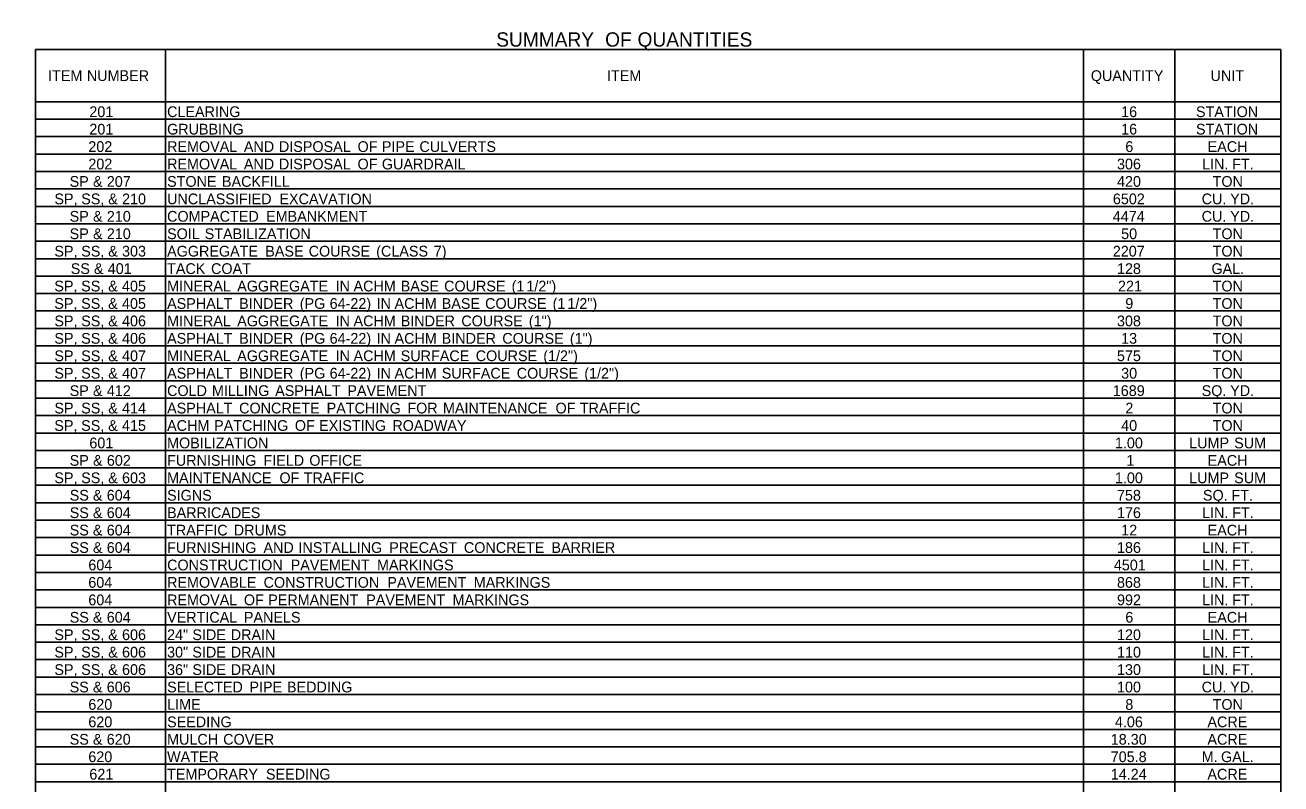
# Model space of a CAD drawing. Extents: x 1955554 to 1962042, y 565952 to 568347.
# Drawn here: x 1960905 to 1961607, y 566475 to 566899 of the extents above; entities that cross this region are included whole.
import ezdxf

# ---------------------------------------------------------------- set-up
doc = ezdxf.new("R2010")
doc.units = 0
doc.layers.add('Default', color=7, linetype='Continuous')

msp = doc.modelspace()

# ---------------------------------------------------------------- linework, layer by layer
at = {"layer": 'Default'}
for p, q in [((1960904.85, 566899.44), (1960904.85, 566899.44)), ((1960910.7, 566885.79), (1960983.24, 566885.79)), ((1960910.7, 566885.79), (1961606.85, 566885.79)), ((1960910.7, 566213.04), (1960910.7, 566885.79)), ((1960910.7, 566213.04), (1960910.7, 566885.79)), ((1960983.24, 566310.54), (1960983.24, 566885.79)), ((1961496.48, 566213.04), (1961496.48, 566885.79)), ((1961547.57, 566213.04), (1961547.57, 566885.79)), ((1961547.57, 566310.54), (1961547.57, 566885.79)), ((1961606.85, 566213.04), (1961606.85, 566885.79)), ((1960910.7, 566856.54), (1961606.85, 566856.54)), ((1960983.24, 566310.54), (1960983.24, 566856.54)), ((1961496.48, 566310.54), (1961496.48, 566856.54)), ((1960910.7, 566846.79), (1961606.85, 566846.79)), ((1960910.7, 566837.04), (1961606.85, 566837.04)), ((1960910.7, 566827.29), (1961606.85, 566827.29)), ((1960910.7, 566817.54), (1961606.85, 566817.54)), ((1960910.7, 566807.79), (1961606.85, 566807.79)), ((1960910.7, 566798.04), (1961606.85, 566798.04)), ((1960910.7, 566788.29), (1961606.85, 566788.29)), ((1960910.7, 566778.54), (1961606.85, 566778.54)), ((1960910.7, 566768.79), (1961606.85, 566768.79)), ((1960910.7, 566759.04), (1961606.85, 566759.04)), ((1960910.7, 566749.29), (1961606.85, 566749.29)), ((1960910.7, 566739.54), (1961606.85, 566739.54)), ((1960910.7, 566729.79), (1961606.85, 566729.79)), ((1960910.7, 566720.04), (1961606.85, 566720.04)), ((1960910.7, 566710.29), (1961606.85, 566710.29)), ((1960910.7, 566700.54), (1961606.85, 566700.54)), ((1960910.7, 566690.79), (1961606.85, 566690.79)), ((1960910.7, 566681.04), (1961606.85, 566681.04)), ((1960910.7, 566671.29), (1961606.85, 566671.29)), ((1960910.7, 566661.54), (1961606.85, 566661.54)), ((1960910.7, 566651.79), (1961606.85, 566651.79)), ((1960910.7, 566642.04), (1961606.85, 566642.04)), ((1960910.7, 566632.29), (1961606.85, 566632.29)), ((1960910.7, 566622.54), (1961606.85, 566622.54)), ((1960910.7, 566612.79), (1961606.85, 566612.79)), ((1960910.7, 566603.04), (1961606.85, 566603.04)), ((1960910.7, 566593.29), (1961606.85, 566593.29)), ((1960910.7, 566583.54), (1961606.85, 566583.54)), ((1960910.7, 566573.79), (1961606.85, 566573.79)), ((1960910.7, 566564.04), (1961606.85, 566564.04)), ((1960910.7, 566554.29), (1961606.85, 566554.29)), ((1960910.7, 566544.54), (1961606.85, 566544.54)), ((1960910.7, 566534.79), (1961606.85, 566534.79)), ((1960910.7, 566525.04), (1961606.85, 566525.04)), ((1960910.7, 566515.29), (1961606.85, 566515.29)), ((1960910.7, 566505.54), (1961606.85, 566505.54)), ((1960910.7, 566495.79), (1961606.85, 566495.79)), ((1960910.7, 566486.04), (1961606.85, 566486.04)), ((1960910.7, 566476.29), (1961606.85, 566476.29))]:
    msp.add_line(p, q, dxfattribs=at)

# ---------------------------------------------------------------- texts
for s, height, p in [(' SUMMARY', 8, (1961165.25, 566887.39)), (' OF', 8, (1961226.12, 566887.39)), (' QUANTITIES', 8, (1961244.23, 566887.39)), ('ITEM', 6, (1960917.72, 566868.16)), (' NUMBER', 6, (1960937.15, 566868.16)), ('ITEM', 6, (1961230.15, 566868.16)), ('QUANTITY', 6, (1961500.6, 566868.16)), ('UNIT', 6, (1961567.52, 566868.16)), ('201', 6, (1960940.76, 566847.99)), ('CLEARING', 6, (1960984.22, 566847.99)), ('16', 6, (1961517.56, 566847.99)), ('STATION', 6, (1961559.39, 566847.99)), ('201', 6, (1960940.76, 566838.24)), ('GRUBBING', 6, (1960984.22, 566838.24)), ('16', 6, (1961517.56, 566838.24)), ('STATION', 6, (1961559.39, 566838.24)), ('202', 6, (1960940.21, 566828.49)), ('REMOVAL', 6, (1960984.22, 566828.49)), (' AND', 6, (1961024.92, 566828.49)), (' DISPOSAL', 6, (1961044.5, 566828.49)), (' OF', 6, (1961088.47, 566828.49)), (' PIPE', 6, (1961102.06, 566828.49)), (' CULVERTS', 6, (1961123.04, 566828.49)), ('6', 6, (1961519.89, 566828.49)), ('EACH', 6, (1961565.91, 566828.49)), ('202', 6, (1960940.21, 566818.74)), ('REMOVAL', 6, (1960984.22, 566818.74)), (' AND', 6, (1961024.92, 566818.74)), (' DISPOSAL', 6, (1961044.5, 566818.74)), (' OF', 6, (1961088.47, 566818.74)), (' GUARDRAIL', 6, (1961102.06, 566818.74)), ('306', 6, (1961515.23, 566818.74)), ('LIN.', 6, (1961562.81, 566818.74)), (' FT.', 6, (1961577.45, 566818.74)), ('SP', 6, (1960929.74, 566808.99)), (' &', 6, (1960940.56, 566808.99)), (' 207', 6, (1960948.29, 566808.99)), ('STONE', 6, (1960984.22, 566808.99)), (' BACKFILL', 6, (1961012.66, 566808.99)), ('420', 6, (1961515.24, 566808.99)), ('TON', 6, (1961568.71, 566808.99)), ('SP,', 6, (1960921.23, 566799.24)), (' SS,', 6, (1960933.99, 566799.24)), (' &', 6, (1960949.09, 566799.24)), (' 210', 6, (1960956.82, 566799.24)), ('UNCLASSIFIED', 6, (1960984.22, 566799.24)), (' EXCAVATION', 6, (1961044.8, 566799.24)), ('6502', 6, (1961512.93, 566799.24)), ('CU.', 6, (1961562.58, 566799.24)), (' YD.', 6, (1961576.28, 566799.24)), ('SP', 6, (1960929.75, 566789.49)), (' &', 6, (1960940.57, 566789.49)), (' 210', 6, (1960948.3, 566789.49)), ('COMPACTED', 6, (1960984.22, 566789.49)), (' EMBANKMENT', 6, (1961037.34, 566789.49)), ('4474', 6, (1961512.91, 566789.49)), ('CU.', 6, (1961562.58, 566789.49)), (' YD.', 6, (1961576.28, 566789.49)), ('SP', 6, (1960929.75, 566779.74)), (' &', 6, (1960940.57, 566779.74)), (' 210', 6, (1960948.3, 566779.74)), ('SOIL', 6, (1960984.22, 566779.74)), (' STABILIZATION', 6, (1961003.02, 566779.74)), ('50', 6, (1961517.57, 566779.74)), ('TON', 6, (1961568.71, 566779.74)), ('SP,', 6, (1960921.21, 566769.99)), (' SS,', 6, (1960933.98, 566769.99)), (' &', 6, (1960949.08, 566769.99)), (' 303', 6, (1960956.81, 566769.99)), ('AGGREGATE', 6, (1960984.22, 566769.99)), (' BASE', 6, (1961036.88, 566769.99)), (' COURSE', 6, (1961061.14, 566769.99)), (' (CLASS', 6, (1961098.89, 566769.99)), (' 7)', 6, (1961131.06, 566769.99)), ('2207', 6, (1961512.9, 566769.99)), ('TON', 6, (1961568.71, 566769.99)), ('SS', 6, (1960930.35, 566760.24)), (' &', 6, (1960941.1, 566760.24)), (' 401', 6, (1960948.83, 566760.24)), ('TACK', 6, (1960984.22, 566760.24)), (' COAT', 6, (1961006.56, 566760.24)), ('128', 6, (1961515.22, 566760.24)), ('GAL.', 6, (1961568.03, 566760.24)), ('SP,', 6, (1960921.19, 566750.49)), (' SS,', 6, (1960933.96, 566750.49)), (' &', 6, (1960949.06, 566750.49)), (' 405', 6, (1960956.78, 566750.49)), ('MINERAL', 6, (1960984.22, 566750.49)), (' AGGREGATE', 6, (1961021.19, 566750.49)), (' IN', 6, (1961076.18, 566750.49)), (' ACHM', 6, (1961086.21, 566750.49)), (' BASE', 6, (1961112.59, 566750.49)), (' COURSE', 6, (1961136.84, 566750.49)), (' (1', 6, (1961174.59, 566750.49)), (' 1/2")', 6, (1961182.83, 566750.49)), ('221', 6, (1961515.81, 566750.49)), ('TON', 6, (1961568.71, 566750.49)), ('SP,', 6, (1960921.19, 566740.74)), (' SS,', 6, (1960933.96, 566740.74)), (' &', 6, (1960949.06, 566740.74)), (' 405', 6, (1960956.78, 566740.74)), ('ASPHALT', 6, (1960984.22, 566740.74)), (' BINDER', 6, (1961022.26, 566740.74)), (' (PG', 6, (1961056.15, 566740.74)), (' 64-22)', 6, (1961072.86, 566740.74)), (' IN', 6, (1961099.1, 566740.74)), (' ACHM', 6, (1961109.13, 566740.74)), (' BASE', 6, (1961135.51, 566740.74)), (' COURSE', 6, (1961159.76, 566740.74)), (' (1', 6, (1961197.51, 566740.74)), (' 1/2")', 6, (1961205.75, 566740.74)), ('9', 6, (1961519.88, 566740.74)), ('TON', 6, (1961568.71, 566740.74)), ('SP,', 6, (1960921.21, 566730.99)), (' SS,', 6, (1960933.98, 566730.99)), (' &', 6, (1960949.08, 566730.99)), (' 406', 6, (1960956.81, 566730.99)), ('MINERAL', 6, (1960984.22, 566730.99)), (' AGGREGATE', 6, (1961021.19, 566730.99)), (' IN', 6, (1961076.18, 566730.99)), (' ACHM', 6, (1961086.21, 566730.99)), (' BINDER', 6, (1961112.59, 566730.99)), (' COURSE', 6, (1961146.48, 566730.99)), (' (1")', 6, (1961184.23, 566730.99)), ('308', 6, (1961515.22, 566730.99)), ('TON', 6, (1961568.71, 566730.99)), ('SP,', 6, (1960921.21, 566721.24)), (' SS,', 6, (1960933.98, 566721.24)), (' &', 6, (1960949.08, 566721.24)), (' 406', 6, (1960956.81, 566721.24)), ('ASPHALT', 6, (1960984.22, 566721.24)), (' BINDER', 6, (1961022.26, 566721.24)), (' (PG', 6, (1961056.15, 566721.24)), (' 64-22)', 6, (1961072.86, 566721.24)), (' IN', 6, (1961099.1, 566721.24)), (' ACHM', 6, (1961109.13, 566721.24)), (' BINDER', 6, (1961135.51, 566721.24)), (' COURSE', 6, (1961169.4, 566721.24)), (' (1")', 6, (1961207.15, 566721.24)), ('13', 6, (1961517.56, 566721.24)), ('TON', 6, (1961568.71, 566721.24)), (' (1/2")', 6, (1961192.29, 566711.49)), ('SP,', 6, (1960921.21, 566711.49)), (' SS,', 6, (1960933.98, 566711.49)), (' &', 6, (1960949.08, 566711.49)), (' 407', 6, (1960956.81, 566711.49)), ('MINERAL', 6, (1960984.22, 566711.49)), (' AGGREGATE', 6, (1961021.19, 566711.49)), (' IN', 6, (1961076.18, 566711.49)), (' ACHM', 6, (1961086.21, 566711.49)), (' SURFACE', 6, (1961112.59, 566711.49)), (' COURSE', 6, (1961154.53, 566711.49)), ('575', 6, (1961515.21, 566711.49)), ('TON', 6, (1961568.71, 566711.49)), ('SP,', 6, (1960921.21, 566701.74)), (' SS,', 6, (1960933.98, 566701.74)), (' &', 6, (1960949.08, 566701.74)), (' 407', 6, (1960956.81, 566701.74)), ('ASPHALT', 6, (1960984.22, 566701.74)), (' BINDER', 6, (1961022.26, 566701.74)), (' (PG', 6, (1961056.15, 566701.74)), (' 64-22)', 6, (1961072.86, 566701.74)), (' IN', 6, (1961099.1, 566701.74)), (' ACHM', 6, (1961109.13, 566701.74)), (' SURFACE', 6, (1961135.51, 566701.74)), (' COURSE', 6, (1961177.45, 566701.74)), (' (1/2")', 6, (1961215.21, 566701.74)), ('30', 6, (1961517.57, 566701.74)), ('TON', 6, (1961568.71, 566701.74)), ('SP', 6, (1960929.77, 566691.99)), (' &', 6, (1960940.59, 566691.99)), (' 412', 6, (1960948.32, 566691.99)), ('COLD', 6, (1960984.22, 566691.99)), (' MILLING', 6, (1961007.06, 566691.99)), (' ASPHALT', 6, (1961042.4, 566691.99)), (' PAVEMENT', 6, (1961082.77, 566691.99)), ('1689', 6, (1961512.89, 566691.99)), ('SQ.', 6, (1961562.57, 566691.99)), (' YD.', 6, (1961576.28, 566691.99)), ('SP,', 6, (1960921.23, 566682.24)), (' SS,', 6, (1960934, 566682.24)), (' &', 6, (1960949.09, 566682.24)), (' 414', 6, (1960956.82, 566682.24)), ('ASPHALT', 6, (1960984.22, 566682.24)), (' CONCRETE', 6, (1961022.26, 566682.24)), (' PATCHING', 6, (1961071.19, 566682.24)), (' FOR', 6, (1961116.31, 566682.24)), (' MAINTENANCE', 6, (1961136.22, 566682.24)), (' OF', 6, (1961199.13, 566682.24)), (' TRAFFIC', 6, (1961212.71, 566682.24)), ('2', 6, (1961519.92, 566682.24)), ('TON', 6, (1961568.71, 566682.24)), ('SP,', 6, (1960921.19, 566672.49)), (' SS,', 6, (1960933.96, 566672.49)), (' &', 6, (1960949.06, 566672.49)), (' 415', 6, (1960956.78, 566672.49)), ('ACHM', 6, (1960984.22, 566672.49)), (' PATCHING', 6, (1961008.27, 566672.49)), (' OF', 6, (1961053.4, 566672.49)), (' EXISTING', 6, (1961066.99, 566672.49)), (' ROADWAY', 6, (1961107.92, 566672.49)), ('40', 6, (1961517.57, 566672.49)), ('TON', 6, (1961568.71, 566672.49)), ('601', 6, (1960940.76, 566662.74)), ('MOBILIZATION', 6, (1960984.22, 566662.74)), ('1.00', 6, (1961514.08, 566662.74)), ('LUMP', 6, (1961555.59, 566662.74)), (' SUM', 6, (1961578.51, 566662.74)), ('SP', 6, (1960929.77, 566652.99)), (' &', 6, (1960940.59, 566652.99)), (' 602', 6, (1960948.32, 566652.99)), ('FURNISHING', 6, (1960984.22, 566652.99)), (' FIELD', 6, (1961035.86, 566652.99)), (' OFFICE', 6, (1961061.5, 566652.99)), ('1', 6, (1961520.47, 566652.99)), ('EACH', 6, (1961565.91, 566652.99)), ('SP,', 6, (1960921.21, 566643.24)), (' SS,', 6, (1960933.98, 566643.24)), (' &', 6, (1960949.08, 566643.24)), (' 603', 6, (1960956.81, 566643.24)), ('MAINTENANCE', 6, (1960984.22, 566643.24)), (' OF', 6, (1961044.8, 566643.24)), (' TRAFFIC', 6, (1961058.38, 566643.24)), ('1.00', 6, (1961514.08, 566643.24)), ('LUMP', 6, (1961555.59, 566643.24)), (' SUM', 6, (1961578.51, 566643.24)), ('SS', 6, (1960929.79, 566633.49)), (' &', 6, (1960940.53, 566633.49)), (' 604', 6, (1960948.26, 566633.49)), ('SIGNS', 6, (1960984.22, 566633.49)), ('758', 6, (1961515.22, 566633.49)), ('SQ.', 6, (1961563.28, 566633.49)), (' FT.', 6, (1961576.99, 566633.49)), ('SS', 6, (1960929.79, 566623.74)), (' &', 6, (1960940.53, 566623.74)), (' 604', 6, (1960948.26, 566623.74)), ('BARRICADES', 6, (1960984.22, 566623.74)), ('176', 6, (1961515.23, 566623.74)), ('LIN.', 6, (1961562.81, 566623.74)), (' FT.', 6, (1961577.45, 566623.74)), ('SS', 6, (1960929.79, 566613.99)), (' &', 6, (1960940.53, 566613.99)), (' 604', 6, (1960948.26, 566613.99)), ('TRAFFIC', 6, (1960984.22, 566613.99)), (' DRUMS', 6, (1961019.28, 566613.99)), ('12', 6, (1961517.59, 566613.99)), ('EACH', 6, (1961565.91, 566613.99)), ('SS', 6, (1960929.79, 566604.24)), (' &', 6, (1960940.53, 566604.24)), (' 604', 6, (1960948.26, 566604.24)), ('FURNISHING', 6, (1960984.22, 566604.24)), (' AND', 6, (1961035.86, 566604.24)), (' INSTALLING', 6, (1961055.44, 566604.24)), (' PRECAST', 6, (1961106.16, 566604.24)), (' CONCRETE', 6, (1961147.92, 566604.24)), (' BARRIER', 6, (1961196.85, 566604.24)), ('186', 6, (1961515.23, 566604.24)), ('LIN.', 6, (1961562.81, 566604.24)), (' FT.', 6, (1961577.45, 566604.24)), ('604', 6, (1960940.19, 566594.49)), ('CONSTRUCTION', 6, (1960984.22, 566594.49)), (' PAVEMENT', 6, (1961051.07, 566594.49)), (' MARKINGS', 6, (1961099.35, 566594.49)), ('4501', 6, (1961513.48, 566594.49)), ('LIN.', 6, (1961562.81, 566594.49)), (' FT.', 6, (1961577.45, 566594.49)), ('604', 6, (1960940.19, 566584.74)), ('REMOVABLE', 6, (1960984.22, 566584.74)), (' CONSTRUCTION', 6, (1961035.96, 566584.74)), (' PAVEMENT', 6, (1961105.13, 566584.74)), (' MARKINGS', 6, (1961153.42, 566584.74)), ('868', 6, (1961515.22, 566584.74)), ('LIN.', 6, (1961562.81, 566584.74)), (' FT.', 6, (1961577.45, 566584.74)), ('604', 6, (1960940.19, 566574.99)), ('REMOVAL', 6, (1960984.22, 566574.99)), (' OF', 6, (1961024.92, 566574.99)), (' PERMANENT', 6, (1961038.51, 566574.99)), (' PAVEMENT', 6, (1961093.31, 566574.99)), (' MARKINGS', 6, (1961141.59, 566574.99)), ('992', 6, (1961515.26, 566574.99)), ('LIN.', 6, (1961562.81, 566574.99)), (' FT.', 6, (1961577.45, 566574.99)), ('SS', 6, (1960929.79, 566565.24)), (' &', 6, (1960940.53, 566565.24)), (' 604', 6, (1960948.26, 566565.24)), ('VERTICAL', 6, (1960984.22, 566565.24)), (' PANELS', 6, (1961024.92, 566565.24)), ('6', 6, (1961519.89, 566565.24)), ('EACH', 6, (1961565.91, 566565.24)), ('SP,', 6, (1960921.21, 566555.49)), (' SS,', 6, (1960933.98, 566555.49)), (' &', 6, (1960949.08, 566555.49)), (' 606', 6, (1960956.81, 566555.49)), ('24"', 6, (1960984.22, 566555.49)), (' SIDE', 6, (1960996.12, 566555.49)), (' DRAIN', 6, (1961017.57, 566555.49)), ('120', 6, (1961515.24, 566555.49)), ('LIN.', 6, (1961562.81, 566555.49)), (' FT.', 6, (1961577.45, 566555.49)), ('SP,', 6, (1960921.21, 566545.74)), (' SS,', 6, (1960933.98, 566545.74)), (' &', 6, (1960949.08, 566545.74)), (' 606', 6, (1960956.81, 566545.74)), ('30"', 6, (1960984.22, 566545.74)), (' SIDE', 6, (1960996.12, 566545.74)), (' DRAIN', 6, (1961017.57, 566545.74)), ('110', 6, (1961515.24, 566545.74)), ('LIN.', 6, (1961562.81, 566545.74)), (' FT.', 6, (1961577.45, 566545.74)), ('SP,', 6, (1960921.21, 566535.99)), (' SS,', 6, (1960933.98, 566535.99)), (' &', 6, (1960949.08, 566535.99)), (' 606', 6, (1960956.81, 566535.99)), ('36"', 6, (1960984.22, 566535.99)), (' SIDE', 6, (1960996.12, 566535.99)), (' DRAIN', 6, (1961017.57, 566535.99)), ('130', 6, (1961515.24, 566535.99)), ('LIN.', 6, (1961562.81, 566535.99)), (' FT.', 6, (1961577.45, 566535.99)), ('SS', 6, (1960929.77, 566526.24)), (' &', 6, (1960940.52, 566526.24)), (' 606', 6, (1960948.25, 566526.24)), ('SELECTED', 6, (1960984.22, 566526.24)), (' PIPE', 6, (1961028.04, 566526.24)), (' BEDDING', 6, (1961049.02, 566526.24)), ('100', 6, (1961515.24, 566526.24)), ('CU.', 6, (1961562.58, 566526.24)), (' YD.', 6, (1961576.28, 566526.24)), ('620', 6, (1960940.19, 566516.49)), ('LIME', 6, (1960984.22, 566516.49)), ('8', 6, (1961519.88, 566516.49)), ('TON', 6, (1961568.71, 566516.49)), ('620', 6, (1960940.19, 566506.74)), ('SEEDING', 6, (1960984.22, 566506.74)), ('4.06', 6, (1961514.07, 566506.74)), ('ACRE', 6, (1961565.79, 566506.74)), ('SS', 6, (1960929.78, 566496.99)), (' &', 6, (1960940.53, 566496.99)), (' 620', 6, (1960948.26, 566496.99)), ('MULCH', 6, (1960984.22, 566496.99)), (' COVER', 6, (1961013.35, 566496.99)), ('18.30', 6, (1961511.75, 566496.99)), ('ACRE', 6, (1961565.79, 566496.99)), ('620', 6, (1960940.19, 566487.24)), ('WATER', 6, (1960984.22, 566487.24)), ('705.8', 6, (1961511.73, 566487.24)), ('M.', 6, (1961562.58, 566487.24)), (' GAL.', 6, (1961571.16, 566487.24)), ('621', 6, (1960940.76, 566477.49)), ('TEMPORARY', 6, (1960984.22, 566477.49)), (' SEEDING', 6, (1961037.26, 566477.49)), ('14.24', 6, (1961511.75, 566477.49)), ('ACRE', 6, (1961565.79, 566477.49))]:
    msp.add_text(s, height=height, dxfattribs=at).set_placement(p)

doc.saveas('drawing.dxf')
